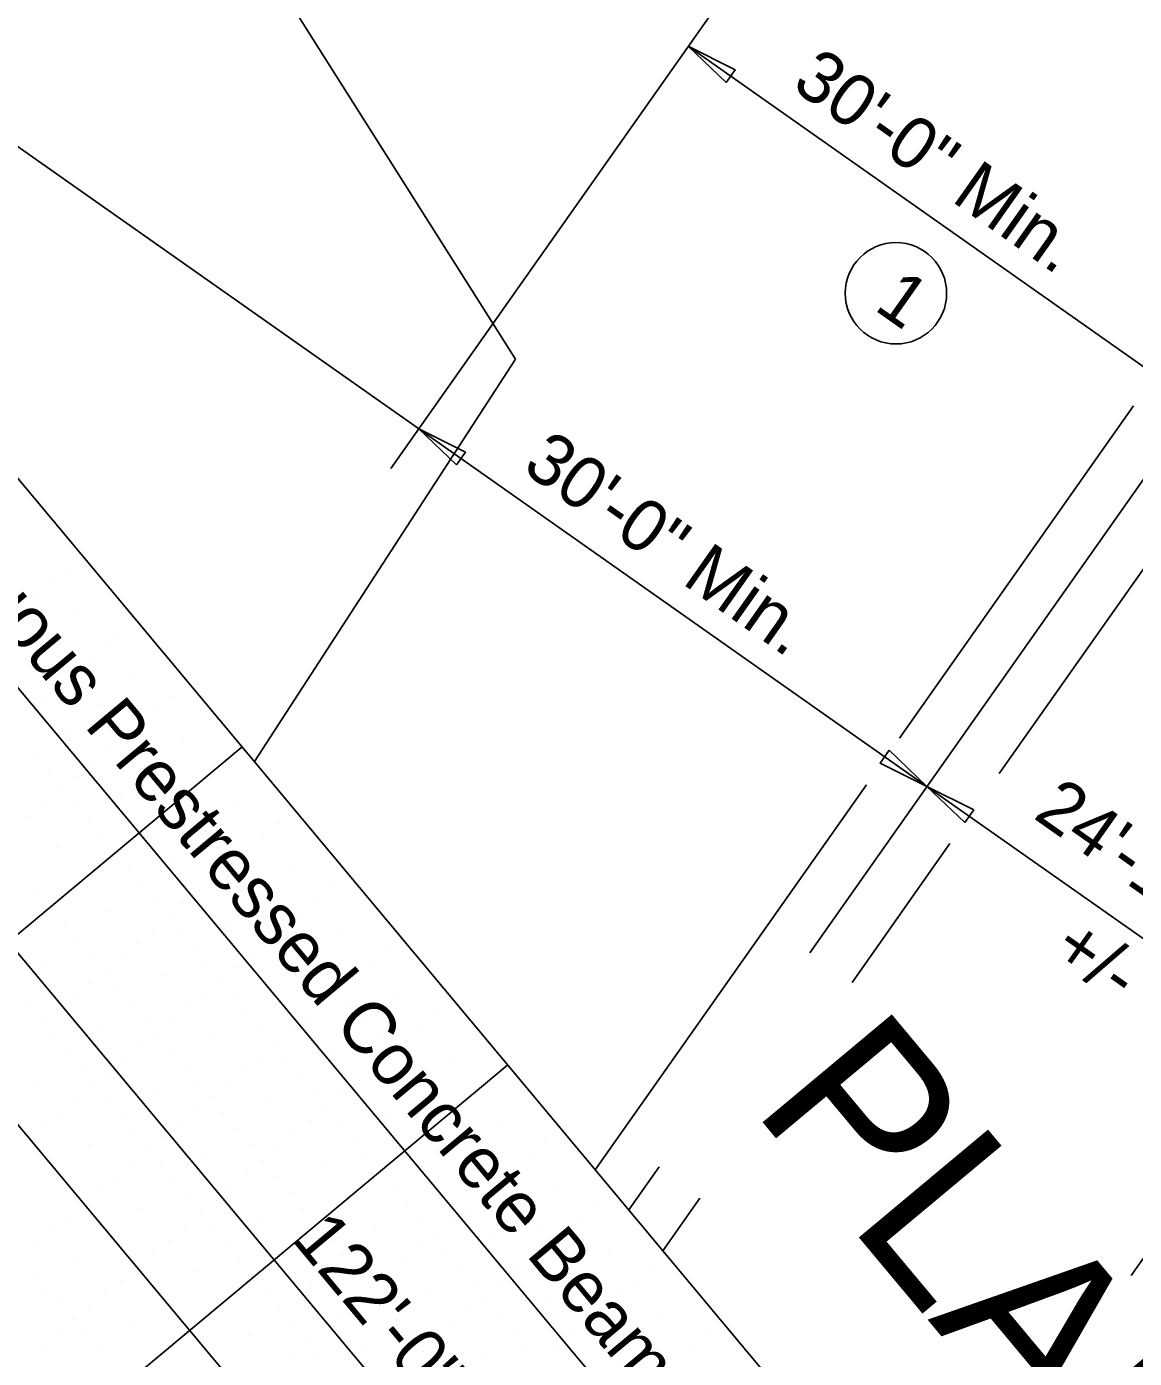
# Model space of a CAD drawing. Extents: x 2042995 to 2043795, y 305365 to 306249.
# Drawn here: x 2043376.4 to 2043429.9, y 305804 to 305868.4 of the extents above; entities that cross this region are included whole.
import ezdxf

# ---------------------------------------------------------------- set-up
doc = ezdxf.new("R2010")
doc.units = 0
for name, color, linetype in [('BR_AUTO DIMENSION', 7, 'Continuous'), ('BR_BORDER LINES', 7, 'Continuous'), ('BR_CENTER LINES', 7, 'Continuous'), ('BR_CONCRETE', 7, 'Continuous'), ('BR_GRID DOTS', 7, 'Continuous'), ('BR_GRID LINES', 7, 'Continuous'), ('BR_PRESTRESSED BEAM', 7, 'Continuous'), ('BR_STRUCTURAL STEEL', 7, 'Continuous'), ('BR_TEXT', 7, 'Continuous'), ('RD_EV_JW', 7, 'Continuous')]:
    doc.layers.add(name, color=color, linetype=linetype)

msp = doc.modelspace()

# ---------------------------------------------------------------- linework, layer by layer
at = {"layer": 'BR_AUTO DIMENSION'}
for p, q in [((2043319.917, 305903.59), (2043477.609, 305714.78)), ((2043408.363, 305867.406), (2043432.893, 305850.135)), ((2043373.969, 305863.994), (2043395.726, 305848.676)), ((2043353.357, 305850.739), (2043431.562, 305757.101)), ((2043395.358, 305848.935), (2043419.888, 305831.664)), ((2043419.888, 305831.664), (2043439.617, 305817.773))]:
    msp.add_line(p, q, dxfattribs=at)
msp.add_lwpolyline([(2043394.005, 305847.013), (2043416.18, 305878.508)], dxfattribs=at)
for points in [[(2043410.192, 305865.661), (2043408.363, 305867.406), (2043410.623, 305866.274)], [(2043397.186, 305847.189), (2043395.358, 305848.935), (2043397.618, 305847.802)], [(2043418.06, 305833.41), (2043419.888, 305831.664), (2043417.628, 305832.796)], [(2043421.716, 305829.918), (2043419.888, 305831.664), (2043422.148, 305830.531)]]:
    msp.add_lwpolyline(points, close=True, dxfattribs=at)
at = {"layer": 'BR_BORDER LINES'}
msp.add_line((2043183.839, 306076.621), (2043615.462, 305559.826), dxfattribs=at)
at = {"layer": 'BR_CENTER LINES'}
for points in [[(2043414.237, 305823.638), (2043467.578, 305899.398), (2043511.813, 305962.173)], [(2043405.497, 305811.224), (2043406.962, 305813.306)]]:
    msp.add_lwpolyline(points, dxfattribs=at)
at = {"layer": 'BR_CONCRETE'}
for points in [[(2043139.109, 306017.548), (2043148.199, 306007.16), (2043160.233, 305993.368), (2043172.245, 305979.557), (2043184.234, 305965.727), (2043196.201, 305951.879), (2043208.145, 305938.012), (2043220.067, 305924.126), (2043231.966, 305910.221), (2043243.843, 305896.297), (2043255.698, 305882.355), (2043267.529, 305868.394), (2043279.339, 305854.414), (2043291.126, 305840.415), (2043302.89, 305826.398), (2043314.632, 305812.361), (2043326.352, 305798.306), (2043338.049, 305784.233), (2043349.724, 305770.14), (2043361.376, 305756.029), (2043373.005, 305741.899), (2043384.613, 305727.75), (2043396.197, 305713.582), (2043407.76, 305699.396), (2043419.299, 305685.191), (2043430.817, 305670.967), (2043442.311, 305656.724), (2043453.784, 305642.463), (2043465.234, 305628.182), (2043476.661, 305613.883), (2043488.066, 305599.566), (2043499.448, 305585.229), (2043510.808, 305570.874), (2043522.146, 305556.5), (2043533.461, 305542.107), (2043544.753, 305527.695), (2043547.219, 305524.543)], [(2043273.14, 305860.139), (2043278.86, 305853.362), (2043290.647, 305839.364), (2043302.411, 305825.346), (2043314.153, 305811.31), (2043325.873, 305797.255), (2043337.57, 305783.181), (2043349.245, 305769.089), (2043360.897, 305754.977), (2043372.526, 305740.847), (2043384.134, 305726.698), (2043395.718, 305712.531), (2043407.281, 305698.344), (2043418.82, 305684.139), (2043425.623, 305675.744)]]:
    msp.add_spline(points, degree=3, dxfattribs=at)
at = {"layer": 'BR_GRID DOTS'}
for p, q in [((2043378.371, 305842.143), (2043378.371, 305842.143)), ((2043377.603, 305841.502), (2043377.603, 305841.502)), ((2043376.836, 305840.861), (2043376.836, 305840.861)), ((2043378.885, 305839.967), (2043378.885, 305839.967)), ((2043376.709, 305839.452), (2043376.709, 305839.452)), ((2043380.935, 305839.073), (2043380.935, 305839.073)), ((2043377.35, 305838.685), (2043377.35, 305838.685)), ((2043380.167, 305838.432), (2043380.167, 305838.432)), ((2043377.991, 305837.917), (2043377.991, 305837.917)), ((2043379.4, 305837.791), (2043379.4, 305837.791)), ((2043378.632, 305837.15), (2043378.632, 305837.15)), ((2043377.865, 305836.509), (2043377.865, 305836.509)), ((2043379.273, 305836.382), (2043379.273, 305836.382)), ((2043381.449, 305836.897), (2043381.449, 305836.897)), ((2043377.097, 305835.868), (2043377.097, 305835.868)), ((2043383.499, 305836.003), (2043383.499, 305836.003)), ((2043379.914, 305835.615), (2043379.914, 305835.615)), ((2043382.731, 305835.362), (2043382.731, 305835.362)), ((2043380.555, 305834.847), (2043380.555, 305834.847)), ((2043381.964, 305834.721), (2043381.964, 305834.721)), ((2043378.379, 305834.333), (2043378.379, 305834.333)), ((2043381.196, 305834.08), (2043381.196, 305834.08)), ((2043384.014, 305833.827), (2043384.014, 305833.827)), ((2043380.429, 305833.439), (2043380.429, 305833.439)), ((2043381.837, 305833.312), (2043381.837, 305833.312)), ((2043376.844, 305833.051), (2043376.844, 305833.051)), ((2043379.661, 305832.798), (2043379.661, 305832.798)), ((2043382.478, 305832.545), (2043382.478, 305832.545)), ((2043377.485, 305832.283), (2043377.485, 305832.283)), ((2043378.894, 305832.157), (2043378.894, 305832.157)), ((2043378.126, 305831.515), (2043378.126, 305831.515)), ((2043380.943, 305831.263), (2043380.943, 305831.263)), ((2043383.12, 305831.777), (2043383.12, 305831.777)), ((2043377.359, 305830.874), (2043377.359, 305830.874)), ((2043378.767, 305830.748), (2043378.767, 305830.748)), ((2043386.578, 305830.757), (2043386.578, 305830.757)), ((2043376.591, 305830.233), (2043376.591, 305830.233)), ((2043379.408, 305829.98), (2043379.408, 305829.98)), ((2043384.402, 305830.242), (2043384.402, 305830.242)), ((2043385.043, 305829.474), (2043385.043, 305829.474)), ((2043388.627, 305829.863), (2043388.627, 305829.863)), ((2043377.873, 305828.698), (2043377.873, 305828.698)), ((2043380.049, 305829.213), (2043380.049, 305829.213)), ((2043385.684, 305828.707), (2043385.684, 305828.707)), ((2043387.86, 305829.221), (2043387.86, 305829.221)), ((2043383.508, 305828.192), (2043383.508, 305828.192)), ((2043387.092, 305828.58), (2043387.092, 305828.58)), ((2043381.331, 305827.678), (2043381.331, 305827.678)), ((2043386.325, 305827.939), (2043386.325, 305827.939)), ((2043389.142, 305827.686), (2043389.142, 305827.686)), ((2043381.973, 305826.91), (2043381.973, 305826.91)), ((2043385.557, 305827.298), (2043385.557, 305827.298)), ((2043386.966, 305827.172), (2043386.966, 305827.172)), ((2043391.191, 305826.792), (2043391.191, 305826.792)), ((2043376.979, 305826.649), (2043376.979, 305826.649)), ((2043382.614, 305826.143), (2043382.614, 305826.143)), ((2043384.79, 305826.657), (2043384.79, 305826.657)), ((2043387.607, 305826.404), (2043387.607, 305826.404)), ((2043390.424, 305826.151), (2043390.424, 305826.151)), ((2043380.437, 305825.628), (2043380.437, 305825.628)), ((2043384.022, 305826.016), (2043384.022, 305826.016)), ((2043388.248, 305825.637), (2043388.248, 305825.637)), ((2043389.656, 305825.51), (2043389.656, 305825.51)), ((2043378.261, 305825.114), (2043378.261, 305825.114)), ((2043383.255, 305825.375), (2043383.255, 305825.375)), ((2043386.072, 305825.122), (2043386.072, 305825.122)), ((2043388.889, 305824.869), (2043388.889, 305824.869)), ((2043378.902, 305824.346), (2043378.902, 305824.346)), ((2043382.487, 305824.734), (2043382.487, 305824.734)), ((2043383.896, 305824.608), (2043383.896, 305824.608)), ((2043388.121, 305824.228), (2043388.121, 305824.228)), ((2043389.53, 305824.102), (2043389.53, 305824.102)), ((2043391.706, 305824.616), (2043391.706, 305824.616)), ((2043379.543, 305823.579), (2043379.543, 305823.579)), ((2043381.72, 305824.093), (2043381.72, 305824.093)), ((2043384.537, 305823.84), (2043384.537, 305823.84)), ((2043387.354, 305823.587), (2043387.354, 305823.587)), ((2043393.755, 305823.722), (2043393.755, 305823.722)), ((2043377.367, 305823.064), (2043377.367, 305823.064)), ((2043380.952, 305823.452), (2043380.952, 305823.452)), ((2043385.178, 305823.073), (2043385.178, 305823.073)), ((2043386.586, 305822.946), (2043386.586, 305822.946)), ((2043390.171, 305823.334), (2043390.171, 305823.334)), ((2043392.988, 305823.081), (2043392.988, 305823.081)), ((2043379.417, 305822.17), (2043379.417, 305822.17)), ((2043380.184, 305822.811), (2043380.184, 305822.811)), ((2043383.002, 305822.558), (2043383.002, 305822.558)), ((2043385.819, 305822.305), (2043385.819, 305822.305)), ((2043390.812, 305822.567), (2043390.812, 305822.567)), ((2043392.22, 305822.44), (2043392.22, 305822.44)), ((2043378.649, 305821.529), (2043378.649, 305821.529)), ((2043380.826, 305822.044), (2043380.826, 305822.044)), ((2043385.051, 305821.664), (2043385.051, 305821.664)), ((2043386.46, 305821.538), (2043386.46, 305821.538)), ((2043388.636, 305822.052), (2043388.636, 305822.052)), ((2043391.453, 305821.799), (2043391.453, 305821.799)), ((2043394.27, 305821.546), (2043394.27, 305821.546)), ((2043376.473, 305821.015), (2043376.473, 305821.015)), ((2043377.882, 305820.888), (2043377.882, 305820.888)), ((2043381.467, 305821.276), (2043381.467, 305821.276)), ((2043384.284, 305821.023), (2043384.284, 305821.023)), ((2043390.685, 305821.158), (2043390.685, 305821.158)), ((2043392.094, 305821.032), (2043392.094, 305821.032)), ((2043377.114, 305820.247), (2043377.114, 305820.247)), ((2043382.108, 305820.509), (2043382.108, 305820.509)), ((2043383.516, 305820.382), (2043383.516, 305820.382)), ((2043387.101, 305820.77), (2043387.101, 305820.77)), ((2043389.918, 305820.517), (2043389.918, 305820.517)), ((2043392.735, 305820.264), (2043392.735, 305820.264)), ((2043396.32, 305820.652), (2043396.32, 305820.652)), ((2043379.932, 305819.994), (2043379.932, 305819.994)), ((2043382.749, 305819.741), (2043382.749, 305819.741)), ((2043387.742, 305820.003), (2043387.742, 305820.003)), ((2043389.15, 305819.876), (2043389.15, 305819.876)), ((2043395.552, 305820.011), (2043395.552, 305820.011)), ((2043377.755, 305819.48), (2043377.755, 305819.48)), ((2043381.981, 305819.1), (2043381.981, 305819.1)), ((2043383.39, 305818.974), (2043383.39, 305818.974)), ((2043385.566, 305819.488), (2043385.566, 305819.488)), ((2043388.383, 305819.235), (2043388.383, 305819.235)), ((2043391.2, 305818.982), (2043391.2, 305818.982)), ((2043393.376, 305819.497), (2043393.376, 305819.497)), ((2043394.784, 305819.37), (2043394.784, 305819.37)), ((2043378.396, 305818.712), (2043378.396, 305818.712)), ((2043381.214, 305818.459), (2043381.214, 305818.459)), ((2043387.615, 305818.594), (2043387.615, 305818.594)), ((2043389.024, 305818.468), (2043389.024, 305818.468)), ((2043394.017, 305818.729), (2043394.017, 305818.729)), ((2043396.834, 305818.476), (2043396.834, 305818.476)), ((2043379.038, 305817.945), (2043379.038, 305817.945)), ((2043380.446, 305817.818), (2043380.446, 305817.818)), ((2043384.031, 305818.206), (2043384.031, 305818.206)), ((2043386.848, 305817.953), (2043386.848, 305817.953)), ((2043389.665, 305817.7), (2043389.665, 305817.7)), ((2043393.249, 305818.088), (2043393.249, 305818.088)), ((2043394.658, 305817.962), (2043394.658, 305817.962)), ((2043376.861, 305817.43), (2043376.861, 305817.43)), ((2043379.679, 305817.177), (2043379.679, 305817.177)), ((2043384.672, 305817.439), (2043384.672, 305817.439)), ((2043386.08, 305817.312), (2043386.08, 305817.312)), ((2043392.482, 305817.447), (2043392.482, 305817.447)), ((2043395.299, 305817.194), (2043395.299, 305817.194)), ((2043378.911, 305816.536), (2043378.911, 305816.536)), ((2043380.32, 305816.41), (2043380.32, 305816.41)), ((2043382.496, 305816.924), (2043382.496, 305816.924)), ((2043385.313, 305816.671), (2043385.313, 305816.671)), ((2043388.13, 305816.418), (2043388.13, 305816.418)), ((2043390.306, 305816.933), (2043390.306, 305816.933)), ((2043391.714, 305816.806), (2043391.714, 305816.806)), ((2043395.94, 305816.427), (2043395.94, 305816.427)), ((2043378.143, 305815.895), (2043378.143, 305815.895)), ((2043384.545, 305816.03), (2043384.545, 305816.03)), ((2043385.954, 305815.904), (2043385.954, 305815.904)), ((2043390.947, 305816.165), (2043390.947, 305816.165)), ((2043393.764, 305815.912), (2043393.764, 305815.912)), ((2043377.376, 305815.254), (2043377.376, 305815.254)), ((2043380.961, 305815.642), (2043380.961, 305815.642)), ((2043383.778, 305815.389), (2043383.778, 305815.389)), ((2043386.595, 305815.136), (2043386.595, 305815.136)), ((2043390.179, 305815.524), (2043390.179, 305815.524)), ((2043391.588, 305815.398), (2043391.588, 305815.398)), ((2043399.398, 305815.406), (2043399.398, 305815.406)), ((2043376.608, 305814.613), (2043376.608, 305814.613)), ((2043381.602, 305814.874), (2043381.602, 305814.874)), ((2043383.01, 305814.748), (2043383.01, 305814.748)), ((2043389.412, 305814.883), (2043389.412, 305814.883)), ((2043392.229, 305814.63), (2043392.229, 305814.63)), ((2043397.222, 305814.892), (2043397.222, 305814.892)), ((2043401.448, 305814.512), (2043401.448, 305814.512)), ((2043379.426, 305814.36), (2043379.426, 305814.36)), ((2043382.243, 305814.107), (2043382.243, 305814.107)), ((2043385.06, 305813.854), (2043385.06, 305813.854)), ((2043387.236, 305814.369), (2043387.236, 305814.369)), ((2043388.644, 305814.242), (2043388.644, 305814.242)), ((2043392.87, 305813.863), (2043392.87, 305813.863)), ((2043397.863, 305814.124), (2043397.863, 305814.124)), ((2043400.68, 305813.871), (2043400.68, 305813.871)), ((2043381.475, 305813.466), (2043381.475, 305813.466)), ((2043382.884, 305813.339), (2043382.884, 305813.339)), ((2043387.877, 305813.601), (2043387.877, 305813.601)), ((2043390.694, 305813.348), (2043390.694, 305813.348)), ((2043398.504, 305813.357), (2043398.504, 305813.357)), ((2043399.913, 305813.23), (2043399.913, 305813.23)), ((2043380.708, 305812.825), (2043380.708, 305812.825)), ((2043383.525, 305812.572), (2043383.525, 305812.572)), ((2043387.109, 305812.96), (2043387.109, 305812.96)), ((2043388.518, 305812.833), (2043388.518, 305812.833)), ((2043396.328, 305812.842), (2043396.328, 305812.842)), ((2043399.145, 305812.589), (2043399.145, 305812.589)), ((2043379.94, 305812.184), (2043379.94, 305812.184)), ((2043386.342, 305812.319), (2043386.342, 305812.319)), ((2043389.159, 305812.066), (2043389.159, 305812.066)), ((2043394.152, 305812.328), (2043394.152, 305812.328)), ((2043398.378, 305811.948), (2043398.378, 305811.948)), ((2043401.962, 305812.336), (2043401.962, 305812.336)), ((2043379.173, 305811.543), (2043379.173, 305811.543)), ((2043381.99, 305811.29), (2043381.99, 305811.29)), ((2043384.166, 305811.804), (2043384.166, 305811.804)), ((2043385.574, 305811.678), (2043385.574, 305811.678)), ((2043389.8, 305811.298), (2043389.8, 305811.298)), ((2043394.793, 305811.56), (2043394.793, 305811.56)), ((2043397.61, 305811.307), (2043397.61, 305811.307)), ((2043399.786, 305811.822), (2043399.786, 305811.822)), ((2043404.012, 305811.442), (2043404.012, 305811.442)), ((2043378.405, 305810.902), (2043378.405, 305810.902)), ((2043384.807, 305811.037), (2043384.807, 305811.037)), ((2043387.624, 305810.784), (2043387.624, 305810.784)), ((2043395.434, 305810.792), (2043395.434, 305810.792)), ((2043396.843, 305810.666), (2043396.843, 305810.666)), ((2043400.427, 305811.054), (2043400.427, 305811.054)), ((2043403.244, 305810.801), (2043403.244, 305810.801)), ((2043377.638, 305810.261), (2043377.638, 305810.261)), ((2043384.039, 305810.396), (2043384.039, 305810.396)), ((2043385.448, 305810.269), (2043385.448, 305810.269)), ((2043393.258, 305810.278), (2043393.258, 305810.278)), ((2043396.075, 305810.025), (2043396.075, 305810.025)), ((2043401.068, 305810.287), (2043401.068, 305810.287)), ((2043402.477, 305810.16), (2043402.477, 305810.16)), ((2043376.87, 305809.62), (2043376.87, 305809.62)), ((2043383.272, 305809.755), (2043383.272, 305809.755)), ((2043386.089, 305809.502), (2043386.089, 305809.502)), ((2043391.082, 305809.763), (2043391.082, 305809.763)), ((2043395.308, 305809.384), (2043395.308, 305809.384)), ((2043398.892, 305809.772), (2043398.892, 305809.772)), ((2043401.709, 305809.519), (2043401.709, 305809.519)), ((2043378.92, 305808.726), (2043378.92, 305808.726)), ((2043382.504, 305809.114), (2043382.504, 305809.114)), ((2043386.73, 305808.734), (2043386.73, 305808.734)), ((2043391.723, 305808.996), (2043391.723, 305808.996)), ((2043394.54, 305808.743), (2043394.54, 305808.743)), ((2043396.716, 305809.257), (2043396.716, 305809.257)), ((2043400.942, 305808.878), (2043400.942, 305808.878)), ((2043402.35, 305808.751), (2043402.35, 305808.751)), ((2043404.526, 305809.266), (2043404.526, 305809.266)), ((2043376.744, 305808.211), (2043376.744, 305808.211)), ((2043381.737, 305808.473), (2043381.737, 305808.473)), ((2043384.554, 305808.22), (2043384.554, 305808.22)), ((2043392.364, 305808.228), (2043392.364, 305808.228)), ((2043393.773, 305808.102), (2043393.773, 305808.102)), ((2043397.357, 305808.49), (2043397.357, 305808.49)), ((2043400.174, 305808.237), (2043400.174, 305808.237)), ((2043406.576, 305808.372), (2043406.576, 305808.372)), ((2043377.385, 305807.444), (2043377.385, 305807.444)), ((2043380.969, 305807.832), (2043380.969, 305807.832)), ((2043390.188, 305807.714), (2043390.188, 305807.714)), ((2043393.005, 305807.461), (2043393.005, 305807.461)), ((2043397.998, 305807.722), (2043397.998, 305807.722)), ((2043399.407, 305807.596), (2043399.407, 305807.596)), ((2043402.991, 305807.984), (2043402.991, 305807.984)), ((2043405.808, 305807.731), (2043405.808, 305807.731)), ((2043380.202, 305807.191), (2043380.202, 305807.191)), ((2043388.012, 305807.199), (2043388.012, 305807.199)), ((2043392.237, 305806.82), (2043392.237, 305806.82)), ((2043395.822, 305807.208), (2043395.822, 305807.208)), ((2043398.639, 305806.955), (2043398.639, 305806.955)), ((2043403.632, 305807.216), (2043403.632, 305807.216)), ((2043405.041, 305807.09), (2043405.041, 305807.09)), ((2043378.026, 305806.676), (2043378.026, 305806.676)), ((2043379.434, 305806.55), (2043379.434, 305806.55)), ((2043388.653, 305806.432), (2043388.653, 305806.432)), ((2043391.47, 305806.179), (2043391.47, 305806.179)), ((2043393.646, 305806.693), (2043393.646, 305806.693)), ((2043397.872, 305806.314), (2043397.872, 305806.314)), ((2043399.28, 305806.187), (2043399.28, 305806.187)), ((2043401.456, 305806.702), (2043401.456, 305806.702)), ((2043404.273, 305806.449), (2043404.273, 305806.449)), ((2043407.09, 305806.196), (2043407.09, 305806.196)), ((2043378.667, 305805.909), (2043378.667, 305805.909)), ((2043381.484, 305805.656), (2043381.484, 305805.656)), ((2043389.294, 305805.664), (2043389.294, 305805.664)), ((2043390.702, 305805.538), (2043390.702, 305805.538)), ((2043394.287, 305805.926), (2043394.287, 305805.926)), ((2043397.104, 305805.673), (2043397.104, 305805.673)), ((2043403.506, 305805.808), (2043403.506, 305805.808)), ((2043404.914, 305805.681), (2043404.914, 305805.681)), ((2043377.899, 305805.268), (2043377.899, 305805.268)), ((2043379.308, 305805.141), (2043379.308, 305805.141)), ((2043387.118, 305805.15), (2043387.118, 305805.15)), ((2043389.935, 305804.897), (2043389.935, 305804.897)), ((2043394.928, 305805.158), (2043394.928, 305805.158)), ((2043396.337, 305805.032), (2043396.337, 305805.032)), ((2043399.921, 305805.42), (2043399.921, 305805.42)), ((2043402.738, 305805.167), (2043402.738, 305805.167)), ((2043405.555, 305804.914), (2043405.555, 305804.914)), ((2043409.14, 305805.302), (2043409.14, 305805.302)), ((2043377.132, 305804.627), (2043377.132, 305804.627)), ((2043379.949, 305804.374), (2043379.949, 305804.374)), ((2043389.167, 305804.256), (2043389.167, 305804.256)), ((2043392.752, 305804.644), (2043392.752, 305804.644)), ((2043395.569, 305804.391), (2043395.569, 305804.391)), ((2043400.562, 305804.652), (2043400.562, 305804.652)), ((2043401.971, 305804.526), (2043401.971, 305804.526)), ((2043408.373, 305804.661), (2043408.373, 305804.661)), ((2043390.576, 305804.129), (2043390.576, 305804.129)), ((2043398.386, 305804.138), (2043398.386, 305804.138)), ((2043406.196, 305804.146), (2043406.196, 305804.146))]:
    msp.add_line(p, q, dxfattribs=at)
at = {"layer": 'BR_GRID LINES'}
for p, q in [((2043168.489, 306063.801), (2043600.112, 305547.005)), ((2043386.831, 305833.574), (2043233.327, 305705.368)), ((2043399.651, 305818.223), (2043246.147, 305690.018))]:
    msp.add_line(p, q, dxfattribs=at)
at = {"layer": 'BR_PRESTRESSED BEAM'}
msp.add_spline([(2043269.336, 305856.962), (2043274.734, 305850.568), (2043286.521, 305836.569), (2043298.285, 305822.551), (2043310.027, 305808.515), (2043321.747, 305794.46), (2043333.444, 305780.386), (2043345.119, 305766.294), (2043356.771, 305752.183), (2043368.4, 305738.053), (2043380.007, 305723.904), (2043391.592, 305709.736), (2043403.154, 305695.55), (2043414.694, 305681.345), (2043421.811, 305672.561)], degree=3, dxfattribs=at)
at = {"layer": 'BR_STRUCTURAL STEEL'}
for p, q in [((2043418.559, 305834), (2043429.863, 305850.051)), ((2043433.887, 305847.217), (2043423.377, 305832.295)), ((2043403.88, 305813.16), (2043416.969, 305831.743)), ((2043420.992, 305828.909), (2043416.271, 305822.206)), ((2043429.742, 305808.043), (2043435.967, 305816.884)), ((2043408.931, 305811.785), (2043407.146, 305809.25))]:
    msp.add_line(p, q, dxfattribs=at)
at = {"layer": 'BR_TEXT'}
msp.add_circle((2043418.391, 305855.479), 2.447, dxfattribs=at)
at = {"layer": 'RD_EV_JW'}
for p, q in [((2043356.34, 305921.363), (2043400.027, 305852.296)), ((2043400.027, 305852.296), (2043387.423, 305832.864))]:
    msp.add_line(p, q, dxfattribs=at)

# ---------------------------------------------------------------- texts
at = {"layer": 'BR_AUTO DIMENSION'}
for s, p in [('246\'-0" Continuous Prestressed Concrete Beam (FIB-54) Bridge Out-To-Out', (2043360.493, 305856.957)), ('122\'-0" Span 2', (2043389.189, 305809.786))]:
    msp.add_text(s, height=2.5, rotation=309.86836, dxfattribs=at).set_placement(p)
at = {"layer": 'BR_TEXT'}
for s, height, rotation, p in [('30\'-0" Min.', 2.5, 324.8166, (2043413.288, 305865.409)), ('1', 2.5, 324.85143, (2043417.277, 305854.724)), ('30\'-0" Min.', 2.5, 324.8166, (2043400.282, 305846.937)), ('24\'-1 1/2"', 2.5, 324.8166, (2043424.959, 305830.174)), ('+/-', 2.5, 324.8166, (2043425.792, 305823.47)), ('PLAN', 8.1251, 309.86836, (2043411.383, 305816.135))]:
    msp.add_text(s, height=height, rotation=rotation, dxfattribs=at).set_placement(p)

doc.saveas('drawing.dxf')
